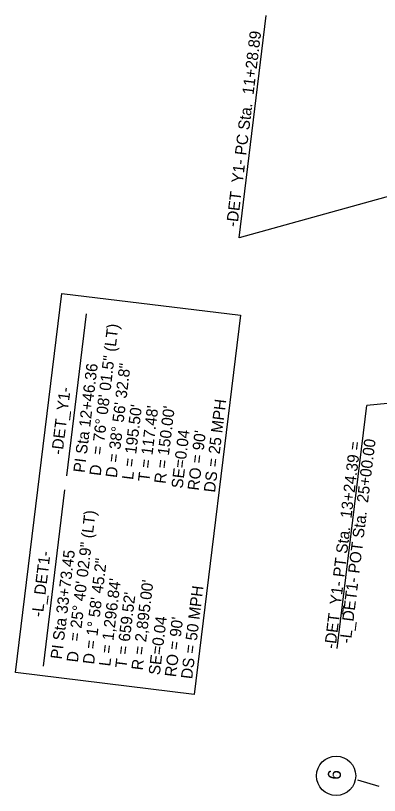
# Model space of a CAD drawing. Extents: x 473658 to 481584, y 489119 to 506230.
# Drawn here: x 480879.2 to 481102.1, y 490537.9 to 491016.2 of the extents above; entities that cross this region are included whole.
import ezdxf

# ---------------------------------------------------------------- set-up
doc = ezdxf.new("R2010")
doc.units = 0
for name, color, linetype in [('Default', 7, 'Continuous'), ('Prop Grid Mask', 7, 'Continuous'), ('Prop Horizontal Alignment Curve and Spiral Data', 7, 'Continuous'), ('Prop Horizontal Alignment Station Label', 7, 'Continuous')]:
    doc.layers.add(name, color=color, linetype=linetype)

msp = doc.modelspace()

# ---------------------------------------------------------------- linework, layer by layer
at = {"layer": 'Default'}
for p, q in [((481075.59, 490549.93), (481075.59, 490549.93)), ((481101.91, 490543.45), (481088.89, 490547.24))]:
    msp.add_line(p, q, dxfattribs=at)
msp.add_circle((481075.59, 490549.93), 12, dxfattribs=at)
at = {"layer": 'Prop Grid Mask'}
msp.add_lwpolyline([(480988.61, 490599.89), (480879.2, 490613.25), (480907.6, 490845.74), (481017.01, 490832.38)], close=True, dxfattribs=at)
at = {"layer": 'Prop Horizontal Alignment Curve and Spiral Data'}
for p, q in [((480910.5, 490733.87), (480922.63, 490833.16)), ((480896.26, 490617.25), (480909.46, 490725.33))]:
    msp.add_line(p, q, dxfattribs=at)
at = {"layer": 'Prop Horizontal Alignment Station Label'}
for p, q in [((481016.13, 490879.8), (481032.78, 491016.16)), ((481159.29, 490919.73), (481016.13, 490879.8)), ((481296.5, 490798.45), (481094.33, 490776.95)), ((481076.14, 490628.04), (481094.33, 490776.95))]:
    msp.add_line(p, q, dxfattribs=at)

# ---------------------------------------------------------------- texts
at = {"layer": 'Default'}
msp.add_text('6', height=8, rotation=83.0365, dxfattribs=at).set_placement((481078.12, 490547.18))
at = {"layer": 'Prop Horizontal Alignment Curve and Spiral Data'}
for s, rotation, p in [('= 76%%d 08\' 01.5" (LT)', 83.0365, (480932.55, 490746.45)), ('PI Sta 12+46.36', 83.0365, (480921.45, 490735.54)), ('D = 38%%d 56\' 32.8"', 83.0365, (480941.22, 490732.45)), ('-DET_Y1-', 83.0398, (480907.94, 490746.64)), ("L = 195.50'", 83.0365, (480951.14, 490731.23)), ("T = 117.48'", 83.0365, (480961.07, 490730.02)), ("R = 150.00'", 83.0365, (480970.99, 490728.81)), ('DS = 25 MPH', 83.0398, (481001.35, 490723.43)), ('SE=0.04', 83.0398, (480981.5, 490725.85)), ("RO = 90'", 83.0398, (480991.42, 490724.64)), ('D', 83.0365, (480931.29, 490733.66)), ('= 25%%d 40\' 02.9" (LT)', 83.0365, (480918.58, 490632.06)), ('-L_DET1-', 83.0398, (480895.78, 490647.09)), ('PI Sta 33+73.45', 83.0365, (480907.47, 490621.15)), ('D = 1%%d 58\' 45.2"', 83.0365, (480927.24, 490618.05)), ("L = 1,296.84'", 83.0365, (480937.17, 490616.84)), ("R = 2,895.00'", 83.0365, (480957.02, 490614.41)), ("T = 659.52'", 83.0365, (480947.1, 490615.63)), ('DS = 50 MPH', 83.0398, (480987.38, 490609.03)), ('SE=0.04', 83.0398, (480967.52, 490611.46)), ("RO = 90'", 83.0398, (480977.45, 490610.25)), ('D', 83.0365, (480917.32, 490619.26))]:
    msp.add_text(s, height=7, rotation=rotation, dxfattribs=at).set_placement(p)
at = {"layer": 'Prop Horizontal Alignment Station Label'}
for s, p in [('-DET_Y1- PC Sta.  11+28.89', (481015.06, 490886.27)), ('-DET_Y1- PT Sta.  13+24.39 =', (481075.21, 490627.55)), ('-L_DET1- POT Sta.  25+00.00', (481084.56, 490630.89))]:
    msp.add_text(s, height=7, rotation=83.0365, dxfattribs=at).set_placement(p)

doc.saveas('drawing.dxf')
